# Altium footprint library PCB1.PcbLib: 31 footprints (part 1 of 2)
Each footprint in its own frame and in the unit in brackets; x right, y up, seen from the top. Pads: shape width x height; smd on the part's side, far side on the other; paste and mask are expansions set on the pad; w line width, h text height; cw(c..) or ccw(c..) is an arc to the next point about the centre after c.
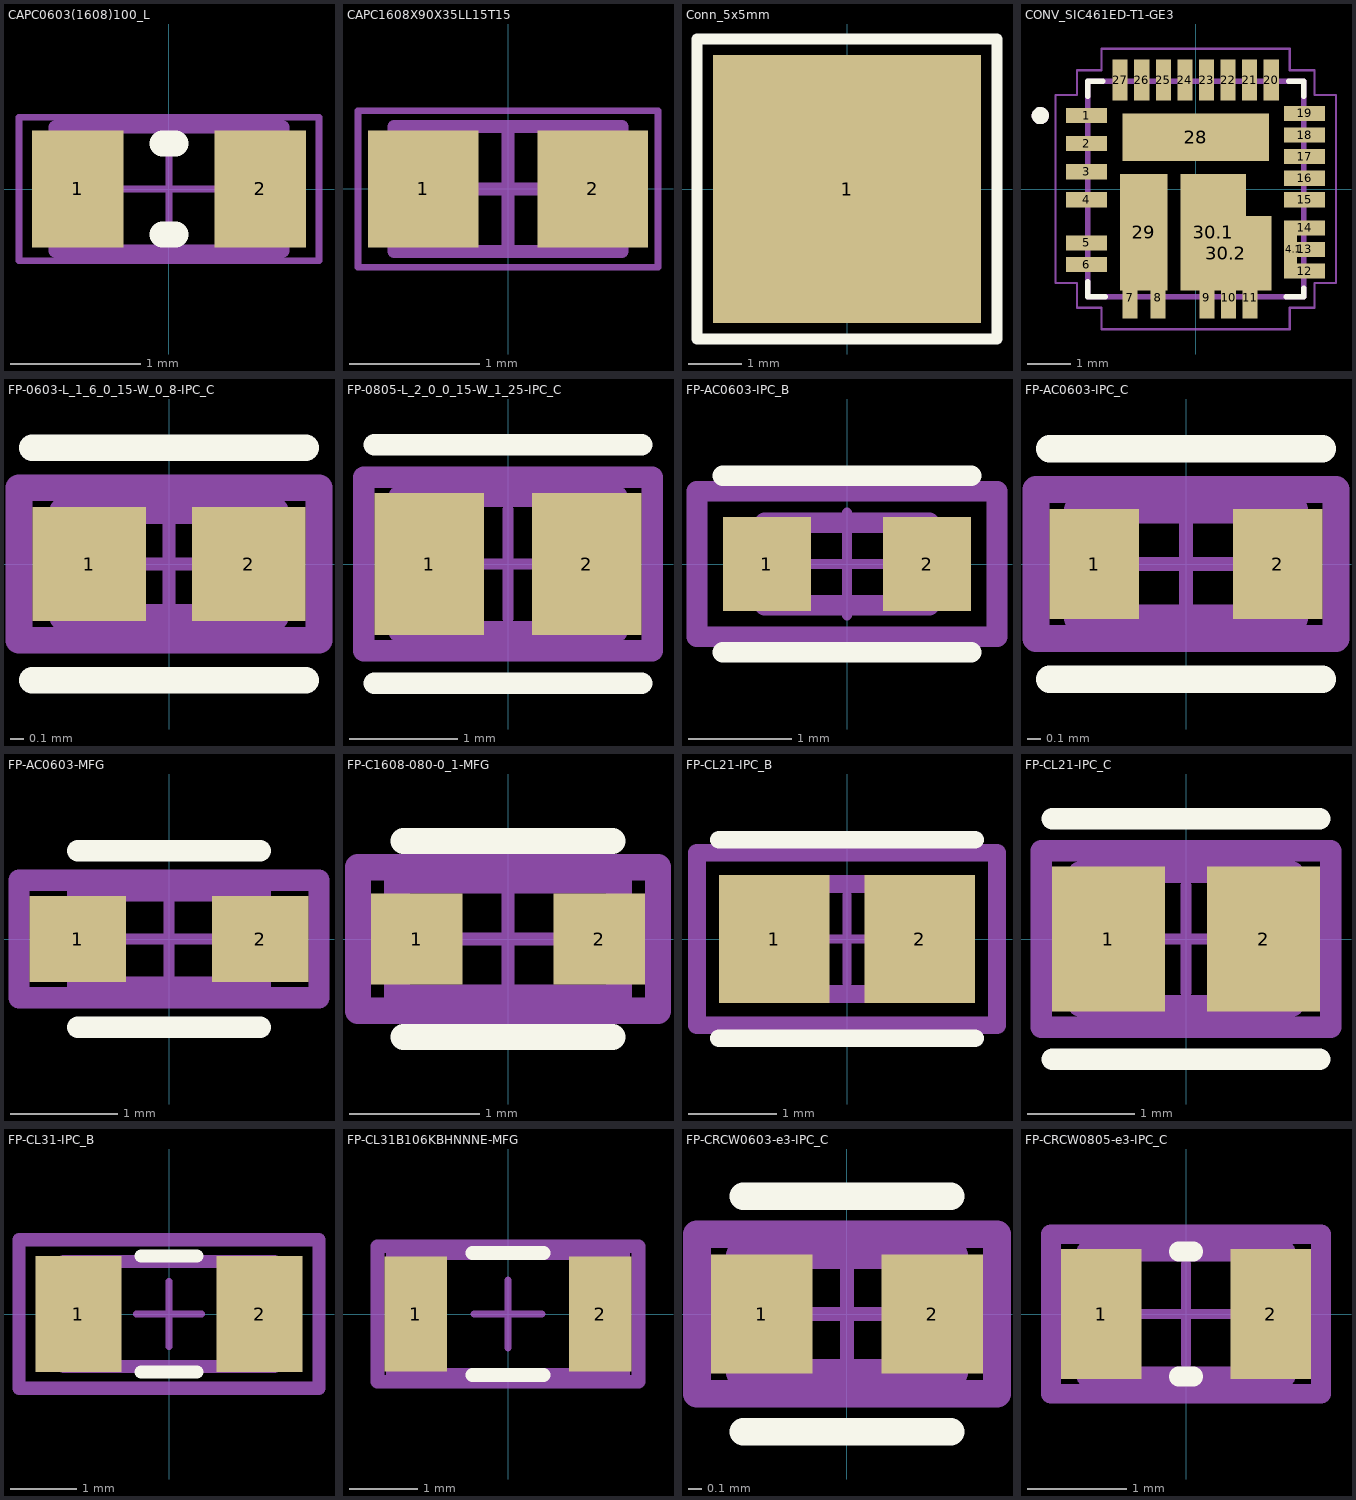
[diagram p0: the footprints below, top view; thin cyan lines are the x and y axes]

## CAPC0603(1608)100_L [mm] "Chip Capacitor, Body 1.6x0.8mm, Height 1.0mm, IPC High Density"
height 1
pads (2):
  rect 0.7x0.9 smd: 1(-0.7,0) 2(0.7,0)
Top Overlay:
  lines w0.2: -0.05,-0.35 0.05,-0.35 ; -0.05,0.35 0.05,0.35
Top 3D Body:
  lines w0.1: -0.875,-0.475 -0.875,0.475 0.875,0.475 0.875,-0.475 -0.875,-0.475
Top Courtyard:
  lines w0.05: -0.475,0 0.475,0 ; 0,-0.475 0,0.475 ; -1.15,-0.55 -1.15,0.55 1.15,0.55 1.15,-0.55 -1.15,-0.55
3D body: height 1, standoff 0, extent -0.525,-0.475 0.525,0.475
3D body: height 1, standoff 0, extent -0.875,-0.475 -0.525,0.475
3D body: height 1, standoff 0, extent 0.525,-0.475 0.875,0.475

## CAPC1608X90X35LL15T15 [mm] "Chip Capacitor, 2-Leads, Body 1.60x0.81mm, IPC High Density"
height 0.9
pads (2):
  rect 0.85x0.9 smd: 1(-0.65,0) 2(0.65,0)
Top 3D Body:
  lines w0.1: -0.875,-0.48 -0.875,0.48 0.875,0.48 0.875,-0.48 -0.875,-0.48
Top Courtyard:
  lines w0.05: -1.15,-0.6 -1.15,0.6 1.15,0.6 1.15,-0.6 -1.15,-0.6
  lines w0.1: -0.48,0 0.48,0 ; 0,-0.48 0,0.48
3D body: height 0.9, standoff 0, extent -0.525,-0.48 0.525,0.48
3D body: height 0.9, standoff 0, extent -0.875,-0.48 -0.525,0.48
3D body: height 0.9, standoff 0, extent 0.525,-0.48 0.875,0.48

## Conn_5x5mm [mm]
pads (1):
  rect 5x5 smd: 1(0,0)
Top Overlay:
  lines w0.2: -2.794,-2.794 -2.794,2.794 2.794,2.794 2.794,-2.794 -2.794,-2.794

## CONV_SIC461ED-T1-GE3 [mm]
pads (32):
  rect 0.95x0.35 smd: 1(-2.525,1.7) 2(-2.525,1.05) 3(-2.525,0.4) 4(-2.525,-0.25) 5(-2.525,-1.25) 6(-2.525,-1.75) 12(2.525,-1.9) 13(2.525,-1.4) 14(2.525,-0.9) 15(2.525,-0.25) 16(2.525,0.25) 17(2.525,0.75) 18(2.525,1.25) 19(2.525,1.75)
  rect 0.35x0.95 smd: 7(-1.52,-2.525) 8(-0.87,-2.525) 9(0.26,-2.525) 10(0.76,-2.525) 11(1.26,-2.525) 20(1.75,2.525) 21(1.25,2.525) 22(0.75,2.525) 23(0.25,2.525) 24(-0.25,2.525) 25(-0.75,2.525) 26(-1.25,2.525) 27(-1.75,2.525)
  rect 0.3x1.35 smd: 14.1(2.2,-1.4)
  rect 3.4x1.1 smd: 28(0,1.2)
  rect 1.1x2.7 smd: 29(-1.2,-1)
  rect 1.52x2.7 smd: 30.1(0.41,-1)
  rect 2.1x1.73 smd: 30.2(0.7,-1.485)
Top Overlay:
  circle w0.2: c-3.6,1.7 r0.1
  lines w0.127: -2.5,-2.15 -2.5,-2.5 -2.1,-2.5 ; -2.5,2.15 -2.5,2.5 -2.15,2.5 ; 2.1,-2.5 2.5,-2.5 2.5,-2.3 ; 2.15,2.5 2.5,2.5 2.5,2.15
Top 3D Body:
  circle w0.2: c-3.6,1.7 r0.1
  lines w0.127: -2.5,2.5 2.5,2.5 ; -2.5,2.5 2.5,2.5 ; -2.5,2.5 -2.5,-2.5 2.5,-2.5 2.5,2.5
Top Courtyard:
  lines w0.05: -3.25,-2.18 -3.25,2.18 -2.75,2.18 -2.75,2.75 -2.18,2.75 -2.18,3.25 2.18,3.25 2.18,2.75 2.75,2.75 2.75,2.18 3.25,2.18 3.25,-2.18 2.75,-2.18 2.75,-2.75 2.18,-2.75 2.18,-3.25 -2.18,-3.25 -2.18,-2.75 -2.75,-2.75 -2.75,-2.18 -3.25,-2.18
3D body "SIC461.step": height 0.8, standoff 0, extent -2.5,-2.5 2.5,2.5

## FP-0603-L_1_6_0_15-W_0_8-IPC_C [mm]
pads (2):
  rect 0.858x0.862 smd paste+0 mask+0: 1(-0.602,0) 2(0.602,0)
Top Overlay:
  lines w0.2: -1.031,-0.875 1.031,-0.875 ; -1.031,0.875 1.031,0.875
Top Assembly:
  lines w0.2: -1.131,-0.575 1.131,-0.575 1.131,0.575 -1.131,0.575 -1.131,-0.575
  text ".Designator" at 0,0.188 h1
Top 3D Body:
  lines w0.2: -0.8,-0.4 0.8,-0.4 0.8,0.4 -0.8,0.4 -0.8,-0.4
Top Courtyard:
  lines w0.2: -1.131,-0.575 1.131,-0.575 1.131,0.575 -1.131,0.575 -1.131,-0.575
Top Component Center:
  lines w0.1: -0.5,0 0.5,0 ; 0,-0.5 0,0.5
3D body "Cap_Taiyo_Yuden_EMK107ABJ475KA-T_eec.STEP": height 0.25, standoff 0, extent -1.131,-0.575 1.131,0.575

## FP-0805-L_2_0_0_15-W_1_25-IPC_C [mm]
pads (2):
  rect 1.008x1.312 smd paste+0 mask+0: 1(-0.727,0) 2(0.727,0)
Top Overlay:
  lines w0.2: -1.231,-1.1 1.231,-1.1 ; -1.231,1.1 1.231,1.1
Top Assembly:
  lines w0.2: -1.331,-0.8 1.331,-0.8 1.331,0.8 -1.331,0.8 -1.331,-0.8
  text ".Designator" at 0,0.188 h1
Top 3D Body:
  lines w0.2: -1,-0.625 1,-0.625 1,0.625 -1,0.625 -1,-0.625
Top Courtyard:
  lines w0.2: -1.331,-0.8 1.331,-0.8 1.331,0.8 -1.331,0.8 -1.331,-0.8
Top Component Center:
  lines w0.1: -0.5,0 0.5,0 ; 0,-0.5 0,0.5
3D body "Cap_Taiyo_Yuden_LMK212ABJ106KGHT_eec.STEP": height 0.25, standoff 0, extent -1.331,-0.8 1.331,0.8

## FP-AC0603-IPC_B [mm]
pads (2):
  rect 0.859x0.912 smd paste+0 mask+0: 1(-0.777,0) 2(0.777,0)
Top Overlay:
  lines w0.2: -1.206,-0.856 1.206,-0.856 ; -1.206,0.856 1.206,0.856
Top Assembly:
  lines w0.2: -1.456,-0.706 1.456,-0.706 1.456,0.706 -1.456,0.706 -1.456,-0.706
  text ".Designator" at 0,0.188 h1
Top 3D Body:
  lines w0.2: -0.8,-0.4 0.8,-0.4 0.8,0.4 -0.8,0.4 -0.8,-0.4
Top Courtyard:
  lines w0.2: -1.456,-0.706 1.456,-0.706 1.456,0.706 -1.456,0.706 -1.456,-0.706
Top Component Center:
  lines w0.1: -0.5,0 0.5,0 ; 0,-0.5 0,0.5
3D body "Res_Yageo_AC0603FR-07180RL_eec.STEP": height 0.25, standoff 0, extent -1.456,-0.706 1.456,0.706

## FP-AC0603-IPC_C [mm]
pads (2):
  rect 0.659x0.812 smd paste+0 mask+0: 1(-0.677,0) 2(0.677,0)
Top Overlay:
  lines w0.2: -1.006,-0.85 1.006,-0.85 ; -1.006,0.85 1.006,0.85
Top Assembly:
  lines w0.2: -1.106,-0.55 1.106,-0.55 1.106,0.55 -1.106,0.55 -1.106,-0.55
  text ".Designator" at 0,0.188 h1
Top 3D Body:
  lines w0.2: -0.8,-0.4 0.8,-0.4 0.8,0.4 -0.8,0.4 -0.8,-0.4
Top Courtyard:
  lines w0.2: -1.106,-0.55 1.106,-0.55 1.106,0.55 -1.106,0.55 -1.106,-0.55
Top Component Center:
  lines w0.1: -0.5,0 0.5,0 ; 0,-0.5 0,0.5
3D body "Res_Yageo_AC0603FR-07180RL_eec.STEP": height 0.25, standoff 0, extent -1.106,-0.55 1.106,0.55

## FP-AC0603-MFG [mm]
pads (2):
  rect 0.9x0.8 smd paste+0 mask+0: 1(-0.85,0) 2(0.85,0)
Top Overlay:
  lines w0.2: -0.85,-0.825 0.85,-0.825 ; -0.85,0.825 0.85,0.825
Top Assembly:
  lines w0.2: -1.4,-0.55 1.4,-0.55 1.4,0.55 -1.4,0.55 -1.4,-0.55
  text ".Designator" at 0,0.188 h1
Top 3D Body:
  lines w0.2: -0.85,-0.45 0.85,-0.45 0.85,0.45 -0.85,0.45 -0.85,-0.45
Top Courtyard:
  lines w0.2: -1.4,-0.55 1.4,-0.55 1.4,0.55 -1.4,0.55 -1.4,-0.55
Top Component Center:
  lines w0.1: -0.5,0 0.5,0 ; 0,-0.5 0,0.5
3D body "Res_Yageo_AC0603FR-07180RL_eec.STEP": height 0.25, standoff 0, extent -1.4,-0.55 1.4,0.55

## FP-C1608-080-0_1-MFG [mm]
pads (2):
  rect 0.7x0.7 smd paste+0 mask+0: 1(-0.7,0) 2(0.7,0)
Top Overlay:
  lines w0.2: -0.8,-0.75 0.8,-0.75 ; -0.8,0.75 0.8,0.75
Top Assembly:
  lines w0.2: -1.15,-0.55 1.15,-0.55 1.15,0.55 -1.15,0.55 -1.15,-0.55
  text ".Designator" at 0,0.188 h1
Top 3D Body:
  lines w0.2: -0.85,-0.45 0.85,-0.45 0.85,0.45 -0.85,0.45 -0.85,-0.45
Top Courtyard:
  lines w0.2: -1.15,-0.55 1.15,-0.55 1.15,0.55 -1.15,0.55 -1.15,-0.55
Top Component Center:
  lines w0.1: -0.5,0 0.5,0 ; 0,-0.5 0,0.5
3D body "Cap_TDK_C1608X6S0G106K080AB_eec.STEP": height 0.25, standoff 0, extent -1.15,-0.55 1.15,0.55

## FP-CL21-IPC_B [mm]
pads (2):
  rect 1.255x1.456 smd paste+0 mask+0: 1(-0.826,0) 2(0.826,0)
Top Overlay:
  lines w0.2: -1.453,-1.128 1.453,-1.128 ; -1.453,1.128 1.453,1.128
Top Assembly:
  lines w0.2: -1.703,-0.978 1.703,-0.978 1.703,0.978 -1.703,0.978 -1.703,-0.978
  text ".Designator" at 0,0.188 h1
Top 3D Body:
  lines w0.2: -1,-0.625 1,-0.625 1,0.625 -1,0.625 -1,-0.625
Top Courtyard:
  lines w0.2: -1.703,-0.978 1.703,-0.978 1.703,0.978 -1.703,0.978 -1.703,-0.978
Top Component Center:
  lines w0.1: -0.5,0 0.5,0 ; 0,-0.5 0,0.5
3D body "Cap_Samsung_CL21B273KBANNNC_eec.STEP": height 0.25, standoff 0, extent -1.703,-0.978 1.703,0.978

## FP-CL21-IPC_C [mm]
pads (2):
  rect 1.055x1.356 smd paste+0 mask+0: 1(-0.726,0) 2(0.726,0)
Top Overlay:
  lines w0.2: -1.253,-1.125 1.253,-1.125 ; -1.253,1.125 1.253,1.125
Top Assembly:
  lines w0.2: -1.353,-0.825 1.353,-0.825 1.353,0.825 -1.353,0.825 -1.353,-0.825
  text ".Designator" at 0,0.188 h1
Top 3D Body:
  lines w0.2: -1,-0.625 1,-0.625 1,0.625 -1,0.625 -1,-0.625
Top Courtyard:
  lines w0.2: -1.353,-0.825 1.353,-0.825 1.353,0.825 -1.353,0.825 -1.353,-0.825
Top Component Center:
  lines w0.1: -0.5,0 0.5,0 ; 0,-0.5 0,0.5
3D body "Cap_Samsung_CL21B273KBANNNC_eec.STEP": height 0.25, standoff 0, extent -1.353,-0.825 1.353,0.825

## FP-CL31-IPC_B [mm]
pads (2):
  rect 1.305x1.758 smd paste+0 mask+0: 1(-1.376,0) 2(1.376,0)
Top Overlay:
  lines w0.2: -0.424,-0.879 0.424,-0.879 ; -0.424,0.879 0.424,0.879
Top Assembly:
  lines w0.2: -2.279,-1.129 2.279,-1.129 2.279,1.129 -2.279,1.129 -2.279,-1.129
  text ".Designator" at 0,0.188 h1
Top 3D Body:
  lines w0.2: -1.6,-0.8 1.6,-0.8 1.6,0.8 -1.6,0.8 -1.6,-0.8
Top Courtyard:
  lines w0.2: -2.279,-1.129 2.279,-1.129 2.279,1.129 -2.279,1.129 -2.279,-1.129
Top Component Center:
  lines w0.1: -0.5,0 0.5,0 ; 0,-0.5 0,0.5
3D body "Cap_Samsung_CL31B105KOFNNNE_eec.STEP": height 0.25, standoff 0, extent -2.279,-1.129 2.279,1.129

## FP-CL31B106KBHNNNE-MFG [mm]
pads (2):
  rect 0.925x1.7 smd paste+0 mask+0: 1(-1.362,0) 2(1.362,0)
Top Overlay:
  lines w0.2: -0.525,-0.9 0.525,-0.9 ; -0.525,0.9 0.525,0.9
Top Assembly:
  lines w0.2: -1.925,-1 1.925,-1 1.925,1 -1.925,1 -1.925,-1
  text ".Designator" at 0,0.188 h1
Top 3D Body:
  lines w0.2: -1.7,-0.9 1.7,-0.9 1.7,0.9 -1.7,0.9 -1.7,-0.9
Top Courtyard:
  lines w0.2: -1.925,-1 1.925,-1 1.925,1 -1.925,1 -1.925,-1
Top Component Center:
  lines w0.1: -0.5,0 0.5,0 ; 0,-0.5 0,0.5
3D body "Cap_Samsung_CL31B106KBHNNNE_eec.STEP": height 0.25, standoff 0, extent -1.925,-1 1.925,1

## FP-CRCW0603-e3-IPC_C [mm]
pads (2):
  rect 0.735x0.862 smd paste+0 mask+0: 1(-0.615,0) 2(0.615,0)
Top Overlay:
  lines w0.2: -0.75,-0.85 0.75,-0.85 ; -0.75,0.85 0.75,0.85
Top Assembly:
  lines w0.2: -1.083,-0.575 1.083,-0.575 1.083,0.575 -1.083,0.575 -1.083,-0.575
  text ".Designator" at 0,0.188 h1
Top 3D Body:
  lines w0.2: -0.775,-0.425 0.775,-0.425 0.775,0.425 -0.775,0.425 -0.775,-0.425
Top Courtyard:
  lines w0.2: -1.083,-0.575 1.083,-0.575 1.083,0.575 -1.083,0.575 -1.083,-0.575
Top Component Center:
  lines w0.1: -0.5,0 0.5,0 ; 0,-0.5 0,0.5
3D body "Res_Vishay_CRCW06033M90FKEC_eec.STEP": height 0.25, standoff 0, extent -1.083,-0.575 1.083,0.575

## FP-CRCW0805-e3-IPC_C [mil]
pads (2):
  rect 31.75x51.5 smd paste+0 mask+0: 1(-33.5,0) 2(33.5,0)
Top Overlay:
  lines w7.87: -2.86,-24.61 2.86,-24.61 ; -2.86,24.61 2.86,24.61
Top Assembly:
  lines w7.87: -53.31,-31.5 53.31,-31.5 53.31,31.5 -53.31,31.5 -53.31,-31.5
  text ".Designator" at 0,7.4 h39.37
Top 3D Body:
  lines w7.87: -39.37,-24.61 39.37,-24.61 39.37,24.61 -39.37,24.61 -39.37,-24.61
Top Courtyard:
  lines w7.87: -53.31,-31.5 53.31,-31.5 53.31,31.5 -53.31,31.5 -53.31,-31.5
Top Component Center:
  lines w3.94: -19.68,0 19.68,0 ; 0,-19.68 0,19.68
3D body "Res_Vishay_CRCW0805100KFKEA_eec.STEP": height 10, standoff 0, extent -53.31,-31.5 53.31,31.5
